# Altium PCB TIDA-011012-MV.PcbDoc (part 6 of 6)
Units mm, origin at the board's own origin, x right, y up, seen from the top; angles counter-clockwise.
Board outline 360 x 280 mm, 4 copper layers (Top Layer, Layer 1, Layer 2, Bottom Layer), stack 2.066 mm thick; 566 components, 345 nets, 1738 pads, 2486 vias.
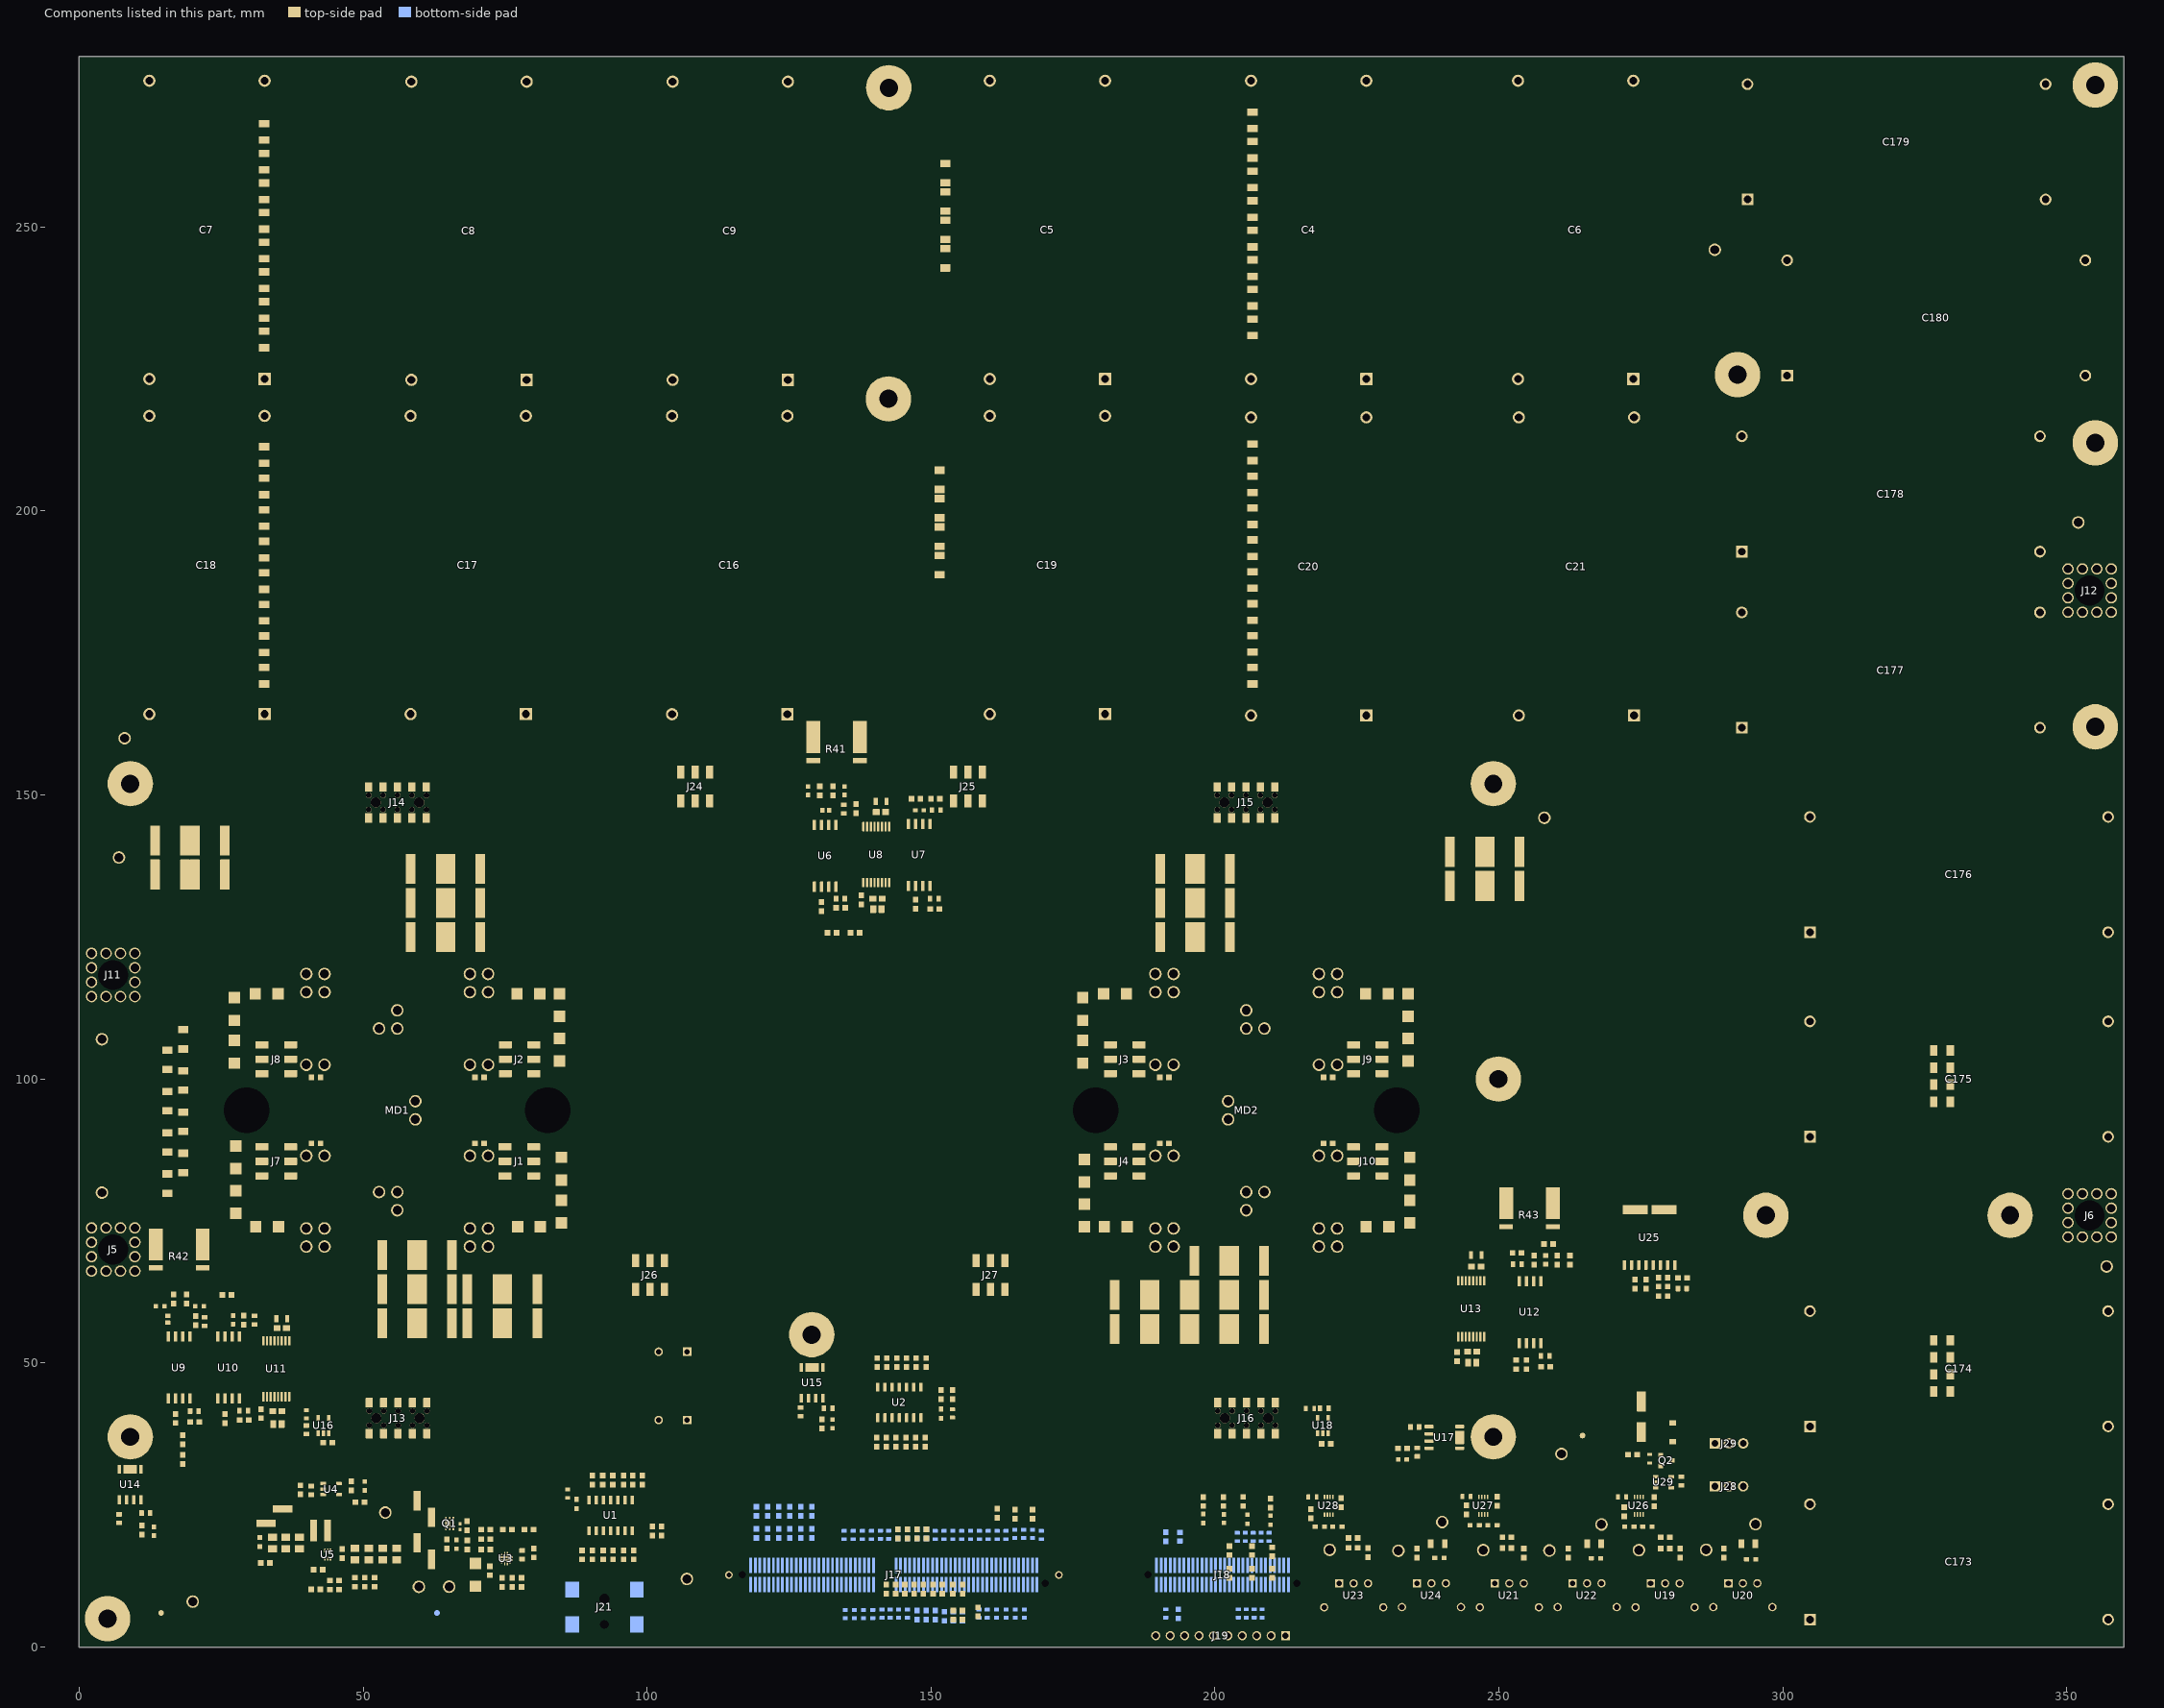
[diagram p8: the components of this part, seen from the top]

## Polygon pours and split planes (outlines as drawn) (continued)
GND_ISO_AC_SENS on Top Layer "TOP_LAYER_GND_ISO_AC_SENS_P234" (solid, remove dead copper, pour order 234): 1,78 11,78 15,74 15,68 11,68 11,64 9,62 1,62
NetC173_2 on Top Layer "TOP_LAYER_NETC173_2_P226" (solid, remove dead copper, pour order 226): 348,150 348,0 360,0 360,150
I_HALL_P on Top Layer "TOP_LAYER_I_HALL_P_P221" (solid, remove dead copper, pour order 221): 302,67 305,70 305,79 301,83 293,83 286,76 277,76 277,92 301,116 301,148 303,150 314,150 316,148 316,0 302,0
I_HALL_N on Top Layer "TOP_LAYER_I_HALL_N_P220" (solid, remove dead copper, pour order 220): 258,87 276,87 276,76 258,76
NetC177_2 on Top Layer "TOP_LAYER_NETC177_2_P216" (solid, remove dead copper, pour order 216): 351,267 348,270 348,273 349,274 349,276 348,277 340,277 340,158 349,158 349,168 360,179 360,193 348,205 348,213 356,221 357,221 357,246 351,252
DC_BUS_NEG on Top Layer "TOP_LAYER_DC_BUS_NEG_P211" (solid, remove dead copper, pour order 211): 80,66 80,54 84,54 84,66
NetC1_1 on Top Layer "TOP_LAYER_NETC1_1_P210" (solid, remove dead copper, pour order 210): 73,65 73,55 76,55 76,65
NetC167_1 on Top Layer "TOP_LAYER_NETC167_1_P209" (solid, remove dead copper, pour order 209): 58,72 58,67 61,67 61,72
DC_BUS_POS on Top Layer "TOP_LAYER_DC_BUS_POS_P208" (solid, remove dead copper, pour order 208): 65,55 65,75 74,75 74,70 73,69 70,69 69,68 69,55
DC_BUS_POS on Top Layer "TOP_LAYER_DC_BUS_POS_P207" (solid, remove dead copper, pour order 207): 4,145 13,145 14,144 14,132 4,132
DC_BUS_NEG on Top Layer "TOP_LAYER_DC_BUS_NEG_P199" (solid, remove dead copper, pour order 199): 54,99 54,91 60,85 60,77 58,75 55,75 54,74 54,54 52,54 52,77 46,83 46,105 54,113 54,123 47,130 29,130 25,134 25,149 16,149 16,156 14,158 2,158 2,168 42,168 47,173 47,210 83,210 83,162 52,162 46,156 46,144 50,140 60,140 60,105
DC_BUS_DAB on Top Layer "TOP_LAYER_DC_BUS_DAB_P201" (solid, remove dead copper, pour order 201): 150,160 150,184 137,184 137,158 147,158 149,160
NetC4_1 on Top Layer "TOP_LAYER_NETC4_1_P205" (solid, remove dead copper, pour order 205): 156,226 156,213 280,213 280,226
NetC4_1 on Top Layer "TOP_LAYER_NETC4_1_P203" (solid, remove dead copper, pour order 203): 5,226 5,213 129,213 129,226
DC_BUS_POS on Top Layer "TOP_LAYER_DC_BUS_POS_P202" (solid, remove dead copper, pour order 202): 67,120 70,120 70,140 79,140 79,123 75,123 75,114 67,114
DC_BUS_NEG on Top Layer "TOP_LAYER_DC_BUS_NEG_P200" (solid, remove dead copper, pour order 200): 100,162 100,210 130,210 130,158 124,158 120,162
5V on Top Layer "TOP_LAYER_5V_P195" (solid, remove dead copper, pour order 195): 243.296,51.928 242.731,51.363 242,51.363 242,48.01 245,48.01 245,52.636 244.344,53.292 244.344,55.463 243.296,55.463 243.293,55.467
GND on Top Layer "TOP_LAYER_GND_P194" (solid, remove dead copper, pour order 194): 248.09,55.42 244.602,55.42 244.602,53.489 245.523,52.569 245.523,49.216 248.09,49.216
5V on Top Layer "TOP_LAYER_5V_P180" (solid, remove dead copper, pour order 180): 138.547,131.883 137.982,131.318 137.191,131.318 137.191,129.153 138.741,129.145 140.375,129.145 140.375,132.467 139.595,133.247 139.595,135.419 138.547,135.419 138.544,135.422
GND on Top Layer "TOP_LAYER_GND_P179" (solid, remove dead copper, pour order 179): 143.341,135.375 139.853,135.375 139.853,133.444 140.773,132.524 140.691,132.442 140.691,129.172 143.341,129.172
5V on Top Layer "TOP_LAYER_5V_P178" (solid, remove dead copper, pour order 178): 32.881,41.37 32.316,40.805 31.525,40.805 31.525,38.64 33.075,38.632 34.709,38.632 34.709,41.954 33.929,42.734 33.929,44.906 32.881,44.906 32.878,44.909
GND on Top Layer "TOP_LAYER_GND_P177" (solid, remove dead copper, pour order 177): 37.675,44.862 34.187,44.862 34.187,42.931 35.108,42.011 35.025,41.929 35.025,38.659 37.675,38.659

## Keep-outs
Keep-Out Layer:
  text ".Layer_Name" at 14.156,-42.206 h1.52

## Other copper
Top Layer:
  pour cut-out: 281.443,75.905 281.155,75.905 281.155,79.997 281.443,79.997
  pour cut-out: 271.517,79.092 271.805,79.092 271.805,75 271.517,75
  text ".Layer_Name" at 14.156,-42.206 h1.52
Layer 1:
  pour cut-out: 136,226 136,212 149,212 149,226
  pour cut-out: 4,42 4,31 14,31 14,42
  pour cut-out: 254,42 243,42 243,32 254,32
  pour cut-out: 124,60 124,49 134,49 134,60
Layer 2:
  pour cut-out: 198,144 198,153 213,153 213,144
  pour cut-out: 49,144 49,153 64,153 64,144
  pour cut-out: 243,32 254,32 254,42 243,42
  pour cut-out: 124,60 124,49 134,49 134,60
  pour cut-out: 4,42 4,31 14,31 14,42
  pour cut-out: 204,89 199,89 199,64 183,64 183,79 173,89 173,99 184,110 184,125 199,125 199,100 205,100 207,98 207,92
  pour cut-out: 58,100 63,100 63,125 79,125 79,110 89,100 89,90 78,79 78,64 63,64 63,89 57,89 55,91 55,97
Bottom Layer:
  pour cut-out: 198,144 198,153 213,153 213,144
  pour cut-out: 49,144 49,153 64,153 64,144
  pour cut-out: 14,31 14,42 4,42 4,31
  pour cut-out: 134,49.1 134,60.1 124,60.1 124,49.1
  pour cut-out: 243,32 254,32 254,42 243,42
  pour cut-out: 133,228 152,228 152,212 133,212
  text ".Layer_Name" at 14.156,-42.206 h1.52

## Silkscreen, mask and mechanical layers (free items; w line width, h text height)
Top Overlay:
  circle w0.254: c254,32 r1.03
  circle w0.254: c254,157 r1.03
  circle w0.254: c4,32 r1.03
  circle w0.254: c4,157 r1.03
  circle w0.254: c29.5,94.5 r4
  circle w0.254: c82.6,94.5 r4
  circle w0.254: c179,94.5 r4
  circle w0.254: c232,94.5 r4
  text "DC_POS" at 60.7,270.2 h3
  text "Danger High Temperature" at 216.7,264.7 h3
  text "Danger High Voltage" at 222.7,258.7 h3
  text "'.PRJ_Number'-.PCB_Rev" at 52,249 h7
  text "2400 VDC, 50 A" at 114.7,179.7 h3
  text "DCDC_NEG" at 327.7,175.2 h3
  text "DC_NEG" at 60.7,167.2 h3
  text "DC_BUS_NEG" at 11.66,158.991 h2
  text "DC_POS" at 102.7,158.033 h2
  text "DC_NEG" at 151.7,158.033 h2
  text "GND" at 68.3,156.3 h1
  text "FLT4" at 72.3,156.3 h1
  text "FLT3" at 77.3,156.3 h1
  text "PWM4" at 82.3,156.3 h1
  text "PWM3" at 87.3,156.3 h1
  text "GND" at 68.3,154.3 h1
  text "RDY" at 72.3,154.3 h1
  text "RST" at 77.928,154.286 h1
  text "5V" at 82.928,154.286 h1
  text "12V" at 87.928,154.286 h1
  text "DC_BUS_POS" at 257.3,151.633 h2
  text "GND" at 216.3,149.3 h1
  text "FLT4" at 220.3,149.3 h1
  text "FLT3" at 225.3,149.3 h1
  text "PWM4" at 230.3,149.3 h1
  text "PWM3" at 235.3,149.3 h1
  text "GND" at 216.3,147.3 h1
  text "RDY" at 220.3,147.3 h1
  text "RST" at 225.928,147.286 h1
  text "5V" at 230.928,147.286 h1
  text "12V" at 235.928,147.286 h1
  text "DC_POS" at 3.367,134.3 h2 r90
  text "DCDC_NEG" at 266.7,133.2 h3
  text "50 A, 1200 VAC" at 3.7,125.7 h3
  text "G" at 67.7,98.7 h2 r180
  text "KS" at 75.7,98.7 h2 r180
  text "G" at 216.7,98.7 h2 r180
  text "KS" at 224.7,98.7 h2 r180
  text "KS" at 37.3,96.3 h2
  text "G" at 45.3,96.3 h2
  text "KS" at 186.3,96.3 h2
  text "G" at 194.3,96.3 h2
  text "G" at 67.7,93.7 h2 r180
  text "KS" at 75.7,93.7 h2 r180
  text "G" at 216.7,93.7 h2 r180
  text "KS" at 224.7,93.7 h2 r180
  text "DCDC_POS" at 266.7,93.2 h3
  text "AC_POS" at 10.8,91.7 h3 r90
  text "KS" at 37.3,91.3 h2
  text "G" at 45.3,91.3 h2
  text "KS" at 186.3,91.3 h2
  text "G" at 194.3,91.3 h2
  text "DC_NEG" at 201.7,83.033 h2
  text "DC_NEG" at 46.699,82.446 h2
  text "DC_POS" at 187.7,77.033 h2
  text "DC_POS" at 62.723,76.15 h2
  text "12V" at 93.3,70.3 h2
  text "DCDC_POS" at 325.7,65.2 h3
  text "GND" at 93.3,58.3 h2
  text "DC_NEG" at 86.967,54.7 h2 r90
  text "DC_NEG" at 179.967,54.7 h2 r90
  text "DC_POS" at 212.967,54.7 h2 r90
  text "DC_POS" at 61.7,49.033 h2
  text "AC_NEG" at 5.8,44.7 h3 r90
  text "12V" at 70.072,42.714 h1 r180
  text "5V" at 75.072,42.714 h1 r180
  text "RST" at 80.072,42.714 h1 r180
  text "12V" at 171.072,42.714 h1 r180
  text "5V" at 176.072,42.714 h1 r180
  text "RST" at 181.072,42.714 h1 r180
  text "RDY" at 85.7,42.7 h1 r180
  text "GND" at 89.7,42.7 h1 r180
  text "RDY" at 186.7,42.7 h1 r180
  text "GND" at 190.7,42.7 h1 r180
  text "PWM3" at 70.7,40.7 h1 r180
  text "PWM4" at 75.7,40.7 h1 r180
  text "FLT3" at 80.7,40.7 h1 r180
  text "FLT4" at 85.7,40.7 h1 r180
  text "GND" at 89.7,40.7 h1 r180
  text "PWM3" at 171.7,40.7 h1 r180
  text "PWM4" at 176.7,40.7 h1 r180
  text "FLT3" at 181.7,40.7 h1 r180
  text "FLT4" at 186.7,40.7 h1 r180
  text "GND" at 190.7,40.7 h1 r180
  text "GND" at 259.441,29.505 h2
  text "'.PRJ_Number'-.PCB_Rev" at 308,12 h7
  text "GND" at 11.66,9.657 h2
  text "GND" at 104.3,7.3 h2
  text "TXD1" at 222.3,7.3 h1
  text "RXD1" at 235.3,7.3 h1
  text "TXD0" at 249.3,7.3 h1
  text "RXD0" at 262.3,7.3 h1
  text "TCLK" at 276.3,7.3 h1
  text "RCLK" at 290.3,7.3 h1
  text ".Layer_Name" at 14.156,-42.206 h1.52
Bottom Overlay:
  text "TXD0" at 252.441,15.475 h1
  text "TXD1" at 224.7,15.3 h1
  text "RXD1" at 237.7,15.3 h1
  text "RXD0" at 264.7,15.3 h1
  text "TCLK" at 279.7,15.3 h1
  text "RCLK" at 292.7,15.3 h1
  text "3V3" at 170.206,6.914 h0.8 r90
  text "SCLK" at 171.761,6.914 h0.8 r90
  text "PICO" at 173.317,6.914 h0.8 r90
  text "POCI" at 174.872,6.914 h0.8 r90
  text "PTE" at 176.428,6.914 h0.8 r90
  text "GPIO1" at 177.983,6.914 h0.8 r90
  text "GPIO2" at 179.539,6.914 h0.8 r90
  text "GPIO3" at 181.094,6.914 h0.8 r90
  text "GPIO4" at 182.65,6.914 h0.8 r90
  text "GND" at 184.206,6.914 h0.8 r90
  text ".Layer_Name" at 14.156,-42.206 h1.52
Top Paste:
  text ".Layer_Name" at 14.156,-42.206 h1.52
Bottom Paste:
  text ".Layer_Name" at 14.156,-42.206 h1.52
Top Solder:
  region: 84.773,215.027 84.773,225.027 54.773,225.027 54.773,215.027
  region: 342.027,219.227 352.027,219.227 352.027,249.227 342.027,249.227
  region: 349.027,85.227 359.027,85.227 359.027,115.227 349.027,115.227
  region: 300.027,85.227 310.027,85.227 310.027,115.227 300.027,115.227
  region: 50,190 50,180 80,180 80,190
  region: 223,191 223,181 283,181 283,191
  region: 50,266 50,256 110,256 110,266
  text ".Layer_Name" at 14.156,-42.206 h1.52
  text ".Layer_Name" at 14.156,-42.206 h1.52
Bottom Solder:
  text ".Layer_Name" at 14.156,-42.206 h1.52
Drill Guide:
  text ".Layer_Name" at 14.156,-42.206 h1.52
M1 Board Outline:
  lines w1: 0,0 0,280 360,280 360,0 0,0 ; 117,69.4 117,122.3 144,122.3 144,69.4 117,69.4
  text ".Layer_Name" at 14.156,-42.206 h1.52
M2 Board Dimensions:
  rectangle: 2.675,-30.56 12.2,-27.385
  rectangle: -0.5,-27.385 2.675,-24.21
  lines w0.178: -0.5,-27.385 24.9,-27.385 ; 2.675,-30.56 2.675,-24.21 ; 5.85,-30.56 5.85,-24.21 ; 12.2,-30.56 12.2,-24.21 ; 18.55,-30.56 18.55,-24.21 ; -0.5,-30.56 -0.5,-24.21 24.9,-24.21 24.9,-30.56 -0.5,-30.56
  text ".Layer_Name" at 14.156,-42.206 h1.52
M3 3D STEP Top:
  lines w0.254: 93,55 170,55 170,162 93,162 93,55 ; 117,70 144,70 144,123 117,123 117,70
  text ".Layer_Name" at 14.156,-42.206 h1.52
M4 3D STEP Bottom:
  text ".Layer_Name" at 14.156,-42.206 h1.52
M5 Assembly Top:
  lines w0.254: -7.917,-44.026 159.723,-44.026 ; -7.917,-38.862 159.774,-38.862 ; -7.917,-33.697 -7.917,-49.191 93.81,-49.191 159.774,-49.191 159.774,-33.697 -7.904,-33.697 -7.904,-49.191 32.114,-49.191 ; 54.694,-49.191 54.694,-33.697 ; 86.876,-38.862 86.876,-33.697 ; 108.212,-38.862 108.212,-33.697 ; 124.011,-49.356 124.011,-44.204
  text "COMPONENTS MARKED 'DNP' SHOULD NOT BE POPULATED." at 28.799,-28.49 h1.52
  text "ASSEMBLY VARIANT:" at 28.786,-31.424 h1.52
  text ".VariantName" at 55.101,-31.424 h1.52
  text "PCB VIEWED FROM TOP SIDE" at -6.304,-37.054 h1.52
  text "BOARD #:" at 56.599,-37.054 h1.52
  text ".PRJ_Number" at 70.455,-37.054 h1.52
  text "REV:" at 91.905,-37.054 h1.52
  text ".PCB_Rev" at 99.309,-37.054 h1.52
  text "SVN REV:" at 113.19,-37.054 h1.52
  text ".VersionControl_RevNumber" at 126.043,-37.054 h1.52
  text "PLOT NAME =" at -6.304,-47.434 h1.52
  text ".plot_File_Name" at 14.156,-47.434 h1.52
  text "GENERATED    :" at 56.65,-47.434 h1.52
  text ".Print_Date" at 78.735,-47.434 h1.52
  text ".Print_Time" at 97.252,-47.434 h1.52
  text "TEXAS INSTRUMENTS" at 129.37,-47.434 h1.52
M6 Assembly Bottom:
  lines w0.254: -7.929,-38.874 159.761,-38.874 ; -7.879,-44.039 159.761,-44.039 ; 27.834,-49.369 27.834,-44.217 ; 43.633,-38.874 43.633,-33.71 ; 64.969,-38.874 64.969,-33.71 ; 97.15,-49.204 97.15,-33.71 ; 119.731,-49.204 159.749,-49.204 159.749,-33.71 -7.929,-33.71 -7.929,-49.204 58.034,-49.204 159.761,-49.204 159.761,-33.71
  text "COMPONENTS MARKED 'DNP' SHOULD NOT BE POPULATED." at 154.491,-28.477 h1.52
  text ".VariantName" at 127.973,-31.424 h1.52
  text "ASSEMBLY VARIANT:" at 154.364,-31.424 h1.52
  text ".VersionControl_RevNumber" at 25.802,-37.067 h1.52
  text "SVN REV:" at 38.654,-37.067 h1.52
  text ".PCB_Rev" at 52.535,-37.067 h1.52
  text "REV:" at 59.939,-37.067 h1.52
  text ".PRJ_Number" at 81.39,-37.067 h1.52
  text "BOARD #:" at 95.245,-37.067 h1.52
  text "PCB VIEWED FROM BOTTOM SIDE" at 158.148,-37.067 h1.52
  text "TEXAS INSTRUMENTS" at 22.474,-47.447 h1.52
  text ".Print_Time" at 54.593,-47.447 h1.52
  text ".Print_Date" at 73.109,-47.447 h1.52
  text "GENERATED    :" at 95.195,-47.447 h1.52
  text ".plot_File_Name" at 137.689,-47.447 h1.52
  text "PLOT NAME =" at 158.148,-47.447 h1.52
M9 Title Sheet:
  drawing of 63 lines, arcs and shapes, not listed
  text "1" at 34.793,446.35 h1.78
  text "2" at 136.266,446.35 h1.78
  text "3" at 237.739,446.35 h1.78
  text "4" at 339.365,446.35 h1.78
  text "5" at 440.923,446.35 h1.78
  text "6" at 542.48,446.35 h1.78
  text "7" at 644.123,446.35 h1.78
  text "8" at 745.596,446.35 h1.78
  text "A" at -12.374,385.441 h1.78
  text "A" at 792.806,385.441 h1.78
  text "B" at -12.374,258.441 h1.78
  text "B" at 792.806,258.441 h1.78
  text "C" at -12.374,131.441 h1.78
  text "C" at 792.806,131.441 h1.78
  text "D" at -12.374,4.441 h1.78
  text "D" at 792.806,4.441 h1.78
  text "PROJECT TITLE:" at 714.447,-13.577 h1.14
  text ".PRJ_Title" at 715.717,-16.964 h1.78
  text "DESIGNED FOR:" at 714.447,-21.223 h1.14
  text ".PRJ_Customer" at 715.717,-24.779 h1.78
  text "FILE NAME:" at 714.447,-28.843 h1.14
  text ".PCB_File_Name_No_Path" at 715.717,-31.891 h1.78
  text "Texas Instruments (TI) and/or its licensors do not warrant the accuracy or completeness of this specification" at 588.221,-36.001 h1.14
  text "ENGINEER:" at 714.447,-36.209 h1.14
  text "LAYOUT BY:" at 752.674,-36.209 h1.14
  text "or any information contained therein. TI and/or its licensors do not warrant that this design will meet" at 587.079,-38.863 h1.14
  text ".PRJ_Engineer" at 715.717,-40.146 h1.78
  text ".PCB_Layout" at 753.956,-40.146 h1.78
  text "the specifications, will be suitable for your application or fit for any particular purpose, or will operate in" at 587.079,-41.725 h1.14
  text ".Layer_Name" at 14.156,-42.206 h1.52
  text "ALTIUM DESIGNER VERSION:" at 752.674,-44.083 h1.14
  text "an implementation. TI and/or its licensors do not warrant that the design is production worthy. You should" at 587.079,-44.587 h1.14
  text "completely validate and test your design implementation to confirm the system functionality for your application." at 588.221,-47.448 h1.14
  text ".print_Scale" at 715.717,-47.469 h1.78
  text ".Application_BuildNumber" at 753.956,-47.469 h1.78
  text "1" at 34.793,-53.903 h1.78
  text "2" at 136.266,-53.903 h1.78
  text "3" at 237.739,-53.903 h1.78
  text "4" at 339.365,-53.903 h1.78
  text "5" at 440.923,-53.903 h1.78
  text "6" at 542.48,-53.903 h1.78
  text "7" at 644.123,-53.903 h1.78
  text "8" at 745.596,-53.903 h1.78
M10 Fab Notes:
  drawing of 189 lines, arcs and shapes, not listed
  text "DESIGN INFORMATION" at 740.876,141.275 h1.52
  text "MIN. TRACK WIDTH:" at 724.504,137.919 h1.52
  text "8" at 752.348,137.919 h1.52
  text "MIL" at 756.279,137.919 h1.52
  text "MIN. CLEARANCE:" at 724.504,134.767 h1.52
  text "7.874" at 748,134.767 h1.52
  text "MIL" at 756.279,134.767 h1.52
  text "MIN. VIA PAD SIZE:" at 724.504,131.614 h1.52
  text "24" at 751.587,131.614 h1.52
  text "MIL" at 756.279,131.614 h1.52
  text "0.05mm (2MIL)" at 742.157,128.314 h1.52
  text "MINIMUM ANNULAR RING" at 716.141,128.106 h1.52
  text "EXTERNAL" at 760.14,128.106 h1.52
  text "PER" at 721.221,125.308 h1.52
  text "IPC-D-275 CLASS 2 LEVEL C" at 726.809,125.308 h1.52
  text "MIL, HOLES" at 764.61,122.756 h1.52
  text "+/-" at 754.642,122.538 h1.52
  text "+/-" at 776.334,122.538 h1.52
  text "REGISTRATION TOLERANCES:" at 716.141,122.511 h1.52
  text "METAL" at 746.616,122.511 h1.52
  text "5" at 761.251,122.511 h1.52
  text "3" at 782.409,122.511 h1.52
  text "MIL" at 785.362,122.511 h1.52
  text "HOLE SIZE TOLERANCE (UNLESS OTHERWISE SPECIFIED):" at 716.141,120.014 h1.52
  text "+/-" at 776.334,119.941 h1.52
  text "3" at 782.409,119.914 h1.52
  text "MIL" at 785.362,119.914 h1.52
  text "MATERIAL:" at 714.242,116.418 h1.52
  text "FR-4 High Tg" at 739.298,113.153 h1.52
  text "X" at 735.629,112.95 h1.52
  text "FR-4" at 724.936,112.835 h1.52
  text "OTHER" at 762.731,112.835 h1.52
  text "62 MIL (1.6mm) +/-10%" at 733.066,109.202 h1.52
  text "X" at 730.016,109.14 h1.52
  text "THICKNESS:" at 716.141,108.994 h1.52
  text "OTHER" at 765.703,108.994 h1.52
  text "TOLERANCE:" at 716.141,105.48 h1.52
  text "X" at 737.687,105.48 h1.52
  text "ANSI IPC-6012 TYPE 3 CLASS 2" at 742.208,105.48 h1.52
  text "OTHER +/-" at 742.208,101.818 h1.52
  text "BOW & TWIST:" at 716.141,98.13 h1.52
  text "X" at 737.687,98.13 h1.52
  text "ANSI IPC-6012 TYPE 3 CLASS 2" at 742.208,98.13 h1.52
  text "OTHER +/-" at 742.208,94.404 h1.52
  text "DRILLING:" at 714.242,91.086 h1.52
  text "NC_DRILL FILES" at 758.972,88.415 h1.52
  text "REFERENCE:" at 716.141,88.315 h1.52
  text "X" at 732.835,88.312 h1.52
  text "AS SHOWN" at 737.356,88.315 h1.52
  text "X" at 755.721,88.315 h1.52
  text "OTHER" at 766.541,84.701 h1.52
  text "PTH COPPER THICKNESS:" at 716.133,84.612 h1.52
  text "X" at 745.07,84.612 h1.52
  text "20-30 um" at 748.321,84.612 h1.52
  text "BOARD FINISH:" at 714.242,80.863 h1.52
  text "SILKSCREEN:" at 718.185,78.066 h1.52
  text "X" at 742.513,78.066 h1.52
  text "TOP" at 745.484,78.066 h1.52
  text "X" at 755.467,78.066 h1.52
  text "BOTTOM" at 758.464,78.066 h1.52
  text "SILKSCREEN COLOR:" at 718.185,74.124 h1.52
  text "X" at 742.487,74.124 h1.52
  text "WHITE" at 745.484,74.124 h1.52
  text "OTHER" at 758.464,74.124 h1.52
  text "X" at 745.815,70.48 h1.52
  text "GREEN" at 748.812,70.48 h1.52
  text "OTHER" at 764.509,70.48 h1.52
  text "SOLDER RESIST COLOR:" at 718.185,70.306 h1.52
  text "X" at 745.815,66.562 h1.52
  text "MATTE" at 748.812,66.562 h1.52
  text "SEMI-GLOSS" at 764.497,66.546 h1.52
  text "IMMERSION GOLD (ENIG)" at 741.192,62.174 h1.52
  text "ENEPIG" at 775.165,61.99 h1.52
  text "SURFACE FINISH:" at 714.242,61.965 h1.52
  text "X" at 736.671,61.965 h1.52
  text "IMM. TIN/SILVER OR EQUIV" at 722.613,58.477 h1.52
  text "OTHER" at 758.972,58.377 h1.52
  text "ARRAY/PANEL:" at 714.242,54.431 h1.52
  text "CUT AND TRIM PER M1 BOARD OUTLINE" at 741.192,54.222 h1.52
  text "N.C. ROUTE" at 741.192,50.768 h1.52
  text "X" at 758.667,50.768 h1.52
  text "V. SCORE" at 763.188,50.768 h1.52
  text "CERTIFICATION:" at 714.242,47.488 h1.52
  text "MATERIALS AND WORKMANSHIP FOR ALL PCBS" at 732.657,47.488 h1.52
  text "TO MEET OR EXCEED THE REQUIREMENTS OF:" at 732.657,45.099 h1.52
  text "X" at 723.45,41.832 h1.52
  text "ANSI IPC-A-600F CLASS ->" at 726.701,41.832 h1.52
  text "X" at 768.56,41.832 h1.52
  text "2" at 771.354,41.832 h1.52
  text "1" at 763.353,41.794 h1.52
  text "3" at 780.346,41.794 h1.52
  text "X" at 744.075,38.081 h1.52
  text "RoHS" at 747.326,38.081 h1.52
  text "OTHER" at 763.694,38.081 h1.52
  text "PER ORDER" at 773.779,38.081 h1.52
  text "ALL BOARDS MUST MEET OR EXCEED UL94-V0 REQUIREMENTS." at 714.942,34.174 h1.52
  text "PCB MUST BEAR THE UL94V-0 UL REGISTERED MATERIAL ID NUMBER" at 714.942,31.226 h1.52
  text "ADDITIONAL REQUIREMENTS:" at 714.242,26.922 h1.52
  text "MICROSECTION:" at 716.141,24.201 h1.52
  text "YES" at 739.147,24.201 h1.52
  text "REQUIRED" at 761.029,20.535 h1.52
  text "BARE BOARD ELEC. TEST:" at 716.141,20.463 h1.52
  text "NONE" at 749.307,20.463 h1.52
  text "X" at 758.032,20.463 h1.52
  text "PER ORDER" at 776.066,20.463 h1.52
  text "XX MIL VIAS REQUIRE NON-CONDUCTIVE FILL AND PLANARIZE" at 720.412,15.257 h1.5
  text "XX MIL VIAS REQUIRE CONDUCTIVE FILL AND PLANARIZE" at 720.616,12.616 h1.52
  text "OUTER XX MIL TRACES REQUIRE 50 OHM SINGLE-ENDED IMPEDANCE" at 720.591,8.466 h1.47
  text "LAYER 2 & 3 (INNER LAYERS) XX MIL WIDE, XX MIL SPACE / TRACES REQUIRE 100 OHM DIFFERENTIAL IMPEDANCE" at 720.387,2.479 h1.52
  text ".Layer_Name" at 14.156,-42.206 h1.52
M11 Gerber Information:
  lines w0.254: -7.917,-44.026 159.723,-44.026 ; -7.917,-38.862 159.774,-38.862 ; -7.917,-33.697 -7.917,-49.191 93.81,-49.191 159.774,-49.191 159.774,-33.697 -7.904,-33.697 -7.904,-49.191 32.114,-49.191 ; 54.694,-49.191 54.694,-33.697 ; 86.876,-38.862 86.876,-33.697 ; 108.212,-38.862 108.212,-33.697 ; 124.011,-49.356 124.011,-44.204
  text "ALL ARTWORK VIEWED FROM TOP SIDE" at -6.304,-37.054 h1.52
  text "BOARD #:" at 56.599,-37.054 h1.52
  text ".PRJ_Number" at 70.455,-37.054 h1.52
  text "REV:" at 91.905,-37.054 h1.52
  text ".PCB_Rev" at 99.309,-37.054 h1.52
  text "SVN REV:" at 113.19,-37.054 h1.52
  text ".VersionControl_RevNumber" at 126.043,-37.054 h1.52
  text "LAYER NAME =" at -6.304,-42.206 h1.52
  text "PLOT NAME =" at -6.304,-47.434 h1.52
  text ".plot_File_Name" at 14.156,-47.434 h1.52
  text "GENERATED    :" at 56.65,-47.434 h1.52
  text ".Print_Date" at 78.735,-47.434 h1.52
  text ".Print_Time" at 97.252,-47.434 h1.52
  text "TEXAS INSTRUMENTS" at 129.37,-47.434 h1.52
M12 Stackup:
  drawing of 295 lines, arcs and shapes, not listed
  text "Layer" at 673.969,437.123 h1.52
  text "Name" at 684.38,437.123 h1.52
  text "Material" at 707.996,437.123 h1.52
  text "Thickness" at 729.834,437.123 h1.52
  text "Constant" at 746.34,437.123 h1.52
  text "Board Layer Stack" at 760.814,437.123 h1.52
  text "Top Overlay" at 684.38,434.075 h1.52
  text "Top Solder" at 684.38,431.027 h1.52
  text "Solder Resist" at 707.996,431.027 h1.52
  text "0,40mil" at 729.834,431.027 h1.52
  text "3.5" at 746.34,431.027 h1.52
  text "1" at 673.969,427.979 h1.52
  text "Top Layer" at 684.38,427.979 h1.52
  text "4,13mil" at 729.834,427.979 h1.52
  text "Dielectric 1" at 684.38,424.931 h1.52
  text "PP-006" at 707.996,424.931 h1.52
  text "2,80mil" at 729.834,424.931 h1.52
  text "4.1" at 746.34,424.931 h1.52
  text "2" at 673.969,421.883 h1.52
  text "Layer 1" at 684.38,421.883 h1.52
  text "CF-004" at 707.996,421.883 h1.52
  text "4,13mil" at 729.834,421.883 h1.52
  text "Dielectric1" at 684.38,418.835 h1.52
  text "FR-4 High Tg" at 707.996,418.835 h1.52
  text "59,20mil" at 729.834,418.835 h1.52
  text "4.8" at 746.34,418.835 h1.52
  text "3" at 673.969,415.787 h1.52
  text "Layer 2" at 684.38,415.787 h1.52
  text "CF-004" at 707.996,415.787 h1.52
  text "4,13mil" at 729.834,415.787 h1.52
  text "Dielectric 2" at 684.38,412.739 h1.52
  text "PP-006" at 707.996,412.739 h1.52
  text "2,80mil" at 729.834,412.739 h1.52
  text "4.1" at 746.34,412.739 h1.52
  text "4" at 673.969,409.691 h1.52
  text "Bottom Layer" at 684.38,409.691 h1.52
  text "4,13mil" at 729.834,409.691 h1.52
  text "Bottom Solder" at 684.38,406.643 h1.52
  text "Solder Resist" at 707.996,406.643 h1.52
  text "0,40mil" at 729.834,406.643 h1.52
  text "3.5" at 746.34,406.643 h1.52
  text "Bottom Overlay" at 684.38,403.595 h1.52
  text ".Layer_Name" at 14.156,-42.206 h1.52
M13 Component Bodies Top:
  text ".Layer_Name" at 14.156,-42.206 h1.52
M14 Component Bodies Bottom:
  text ".Layer_Name" at 14.156,-42.206 h1.52
M15 Courtyards Top:
  text ".Layer_Name" at 14.156,-42.206 h1.52
M16 Courtyards Bottom:
  text ".Layer_Name" at 14.156,-42.206 h1.52
Drill Drawing:
  circle w0.254: c674.439,340.577 r0.421
  circle w0.254: c674.439,340.577 r0.702
  circle w0.254: c674.439,331.104 r0.702
  lines w0.254: 673.738,333.911 674.089,333.911 674.089,333.56 674.79,333.56 674.79,333.911 675.141,333.911 675.141,334.612 674.79,334.612 674.79,334.963 674.089,334.963 674.089,334.612 673.738,334.612 673.738,333.911 ; 673.738,336.717 673.738,337.068 674.089,337.419 673.738,337.77 673.738,338.121 674.089,338.121 674.439,337.77 674.79,338.121 675.141,338.121 675.141,337.77 674.79,337.419 675.141,337.068 675.141,336.717 674.79,336.717 674.439,337.068 674.089,336.717 673.738,336.717 ; 673.738,343.734 674.439,343.032 675.141,343.734 674.439,344.436 673.738,343.734 ; 673.738,347.593 675.141,347.593 674.439,346.19 673.738,347.593 ; 673.738,349.698 674.089,349.698 674.089,349.348 674.79,349.348 674.79,349.698 675.141,349.698 675.141,350.4 674.79,350.4 674.79,350.751 674.089,350.751 674.089,350.4 673.738,350.4 673.738,349.698 ; 673.738,352.856 674.089,352.856 674.439,352.505 674.79,352.856 675.141,352.856 674.79,353.207 675.141,353.558 674.79,353.558 674.439,353.908 674.089,353.558 673.738,353.558 674.089,353.207 673.738,352.856 ; 673.738,356.013 674.089,356.013 674.439,355.663 674.79,356.013 675.141,356.013 674.79,356.364 675.141,356.715 674.79,356.715 674.439,357.066 674.089,356.715 673.738,356.715 674.089,356.364 673.738,356.013 ; 673.738,361.978 675.141,361.978 675.141,363.381 673.738,363.381 673.738,361.978 ; 673.738,368.293 674.439,368.644 675.141,368.293 674.79,368.994 675.141,369.696 674.439,369.345 673.738,369.696 674.089,368.994 673.738,368.293 ; 673.738,371.45 675.141,371.45 675.141,372.854 673.738,372.854 673.738,371.45 ; 673.738,385.484 675.141,385.484 674.439,384.08 673.738,385.484 ; 674.018,347.313 674.86,347.313 674.439,346.471 674.018,347.313 ; 674.018,349.839 674.229,349.839 674.229,349.628 674.65,349.628 674.65,349.839 674.86,349.839 674.86,350.26 674.65,350.26 674.65,350.47 674.229,350.47 674.229,350.26 674.018,350.26 674.018,349.839 ; 674.018,356.154 674.229,356.154 674.439,355.943 674.65,356.154 674.86,356.154 674.65,356.364 674.86,356.575 674.65,356.575 674.439,356.785 674.229,356.575 674.018,356.575 674.229,356.364 674.018,356.154 ; 674.018,368.573 674.439,368.784 674.86,368.573 674.65,368.994 674.86,369.415 674.439,369.205 674.018,369.415 674.229,368.994 674.018,368.573 ; 674.018,371.731 674.86,371.731 674.86,372.573 674.018,372.573 674.018,371.731
  lines w0.305: 672.466,329.455 754.569,329.455 ; 672.466,389.448 754.569,389.448 ; 681.047,326.298 681.047,392.606 ; 689.486,326.298 689.486,392.606 ; 705.657,326.298 705.657,392.606 ; 712.241,326.298 712.241,392.606 ; 721.772,326.298 721.772,392.606 ; 740.177,326.298 740.177,392.606 ; 672.466,326.298 754.569,326.298 754.569,392.606 672.466,392.606 672.466,326.298
  text "Symbol" at 674.36,390.395 h1.83
  text "Quantity" at 681.995,390.395 h1.83
  text "Finished Hole Size" at 690.434,390.395 h1.83
  text "Plated" at 706.604,390.395 h1.83
  text "Hole Type" at 713.188,390.395 h1.83
  text "Drill Layer Pair" at 722.719,390.395 h1.83
  text "Hole Tolerance" at 741.124,390.395 h1.83
  text "40" at 681.995,387.238 h1.52
  text "38,19mil (0,970mm)" at 690.434,387.238 h1.52
  text "NPTH" at 706.604,387.238 h1.52
  text "Round" at 713.188,387.238 h1.52
  text "Top Layer - Bottom Layer" at 722.719,387.238 h1.52
  text "D" at 673.718,386.984 h1.4
  text "4" at 681.995,384.08 h1.52
  text "50,00mil (1,270mm)" at 690.434,384.08 h1.52
  text "NPTH" at 706.604,384.08 h1.52
  text "Round" at 713.188,384.08 h1.52
  text "Top Layer - Bottom Layer" at 722.719,384.08 h1.52
  text "1" at 681.995,380.923 h1.52
  text "62,99mil (1,600mm)" at 690.434,380.923 h1.52
  text "NPTH" at 706.604,380.923 h1.52
  text "Round" at 713.188,380.923 h1.52
  text "Top Layer - Bottom Layer" at 722.719,380.923 h1.52
  text "B" at 673.718,380.669 h1.4
  text "8" at 681.995,377.765 h1.52
  text "70,08mil (1,780mm)" at 690.434,377.765 h1.52
  text "NPTH" at 706.604,377.765 h1.52
  text "Round" at 713.188,377.765 h1.52
  text "Top Layer - Bottom Layer" at 722.719,377.765 h1.52
  text "E" at 673.718,377.512 h1.4
  text "1" at 681.995,374.608 h1.52
  text "70,87mil (1,800mm)" at 690.434,374.608 h1.52
  text "NPTH" at 706.604,374.608 h1.52
  text "Round" at 713.188,374.608 h1.52
  text "Top Layer - Bottom Layer" at 722.719,374.608 h1.52
  text "A" at 673.718,374.354 h1.4
  text "4" at 681.995,371.45 h1.52
  text "208,66mil (5,300mm)" at 690.434,371.45 h1.52
  text "NPTH" at 706.604,371.45 h1.52
  text "Round" at 713.188,371.45 h1.52
  text "Top Layer - Bottom Layer" at 722.719,371.45 h1.52
  text "4" at 681.995,368.293 h1.52
  text "314,96mil (8,000mm)" at 690.434,368.293 h1.52
  text "NPTH" at 706.604,368.293 h1.52
  text "Round" at 713.188,368.293 h1.52
  text "Top Layer - Bottom Layer" at 722.719,368.293 h1.52
  text "2486" at 681.995,365.135 h1.52
  text "7,87mil (0,200mm)" at 690.434,365.135 h1.52
  text "PTH" at 706.604,365.135 h1.52
  text "Round" at 713.188,365.135 h1.52
  text "Top Layer - Bottom Layer" at 722.719,365.135 h1.52
  text "F" at 673.718,364.881 h1.4
  text "2" at 681.995,361.978 h1.52
  text "33,07mil (0,840mm)" at 690.434,361.978 h1.52
  text "PTH" at 706.604,361.978 h1.52
  text "Round" at 713.188,361.978 h1.52
  text "Top Layer - Bottom Layer" at 722.719,361.978 h1.52
  text "4" at 681.995,358.82 h1.52
  text "35,43mil (0,900mm)" at 690.434,358.82 h1.52
  text "PTH" at 706.604,358.82 h1.52
  text "Round" at 713.188,358.82 h1.52
  text "Top Layer - Bottom Layer" at 722.719,358.82 h1.52
  text "C" at 673.718,358.566 h1.4
  text "30" at 681.995,355.663 h1.52
  text "37,40mil (0,950mm)" at 690.434,355.663 h1.52
  text "PTH" at 706.604,355.663 h1.52
  text "Round" at 713.188,355.663 h1.52
  text "Top Layer - Bottom Layer" at 722.719,355.663 h1.52
  text "10" at 681.995,352.505 h1.52
  text "43,31mil (1,100mm)" at 690.434,352.505 h1.52
  text "PTH" at 706.604,352.505 h1.52
  text "Round" at 713.188,352.505 h1.52
  text "Top Layer - Bottom Layer" at 722.719,352.505 h1.52
  text "6" at 681.995,349.348 h1.52
  text "47,24mil (1,200mm)" at 690.434,349.348 h1.52
  text "PTH" at 706.604,349.348 h1.52
  text "Round" at 713.188,349.348 h1.52
  text "Top Layer - Bottom Layer" at 722.719,349.348 h1.52
  text "32" at 681.995,346.19 h1.52
  text "53,15mil (1,350mm)" at 690.434,346.19 h1.52
  text "PTH" at 706.604,346.19 h1.52
  text "Round" at 713.188,346.19 h1.52
  text "Top Layer - Bottom Layer" at 722.719,346.19 h1.52
  text "48" at 681.995,343.032 h1.52
  text "55,12mil (1,400mm)" at 690.434,343.032 h1.52
  text "PTH" at 706.604,343.032 h1.52
  text "Round" at 713.188,343.032 h1.52
  text "Top Layer - Bottom Layer" at 722.719,343.032 h1.52
  text "48" at 681.995,339.875 h1.52
  text "58,07mil (1,475mm)" at 690.434,339.875 h1.52
  text "PTH" at 706.604,339.875 h1.52
  text "Round" at 713.188,339.875 h1.52
  text "Top Layer - Bottom Layer" at 722.719,339.875 h1.52
  text "64" at 681.995,336.717 h1.52
  text "62,99mil (1,600mm)" at 690.434,336.717 h1.52
  text "PTH" at 706.604,336.717 h1.52
  text "Round" at 713.188,336.717 h1.52
  text "Top Layer - Bottom Layer" at 722.719,336.717 h1.52
  text "23" at 681.995,333.56 h1.52
  text "63,00mil (1,600mm)" at 690.434,333.56 h1.52
  text "PTH" at 706.604,333.56 h1.52
  text "Round" at 713.188,333.56 h1.52
  text "Top Layer - Bottom Layer" at 722.719,333.56 h1.52
  text "15" at 681.995,330.402 h1.52
  text "125,98mil (3,200mm)" at 690.434,330.402 h1.52
  text "PTH" at 706.604,330.402 h1.52
  text "Round" at 713.188,330.402 h1.52
  text "Top Layer - Bottom Layer" at 722.719,330.402 h1.52
  text "2830 Total" at 681.995,327.245 h1.52
  text ".Layer_Name" at 14.156,-42.206 h1.52
M17 Embedded Cavity:
  text ".Layer_Name" at 14.156,-42.206 h1.52
M18 Embedded Assembly:
  text ".Layer_Name" at 14.156,-42.206 h1.52
M19 Embedded Keepout:
  text ".Layer_Name" at 14.41,-41.952 h1.52

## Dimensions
-0.5,-30.56 to 24.9,-30.56 on M2 Board Dimensions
